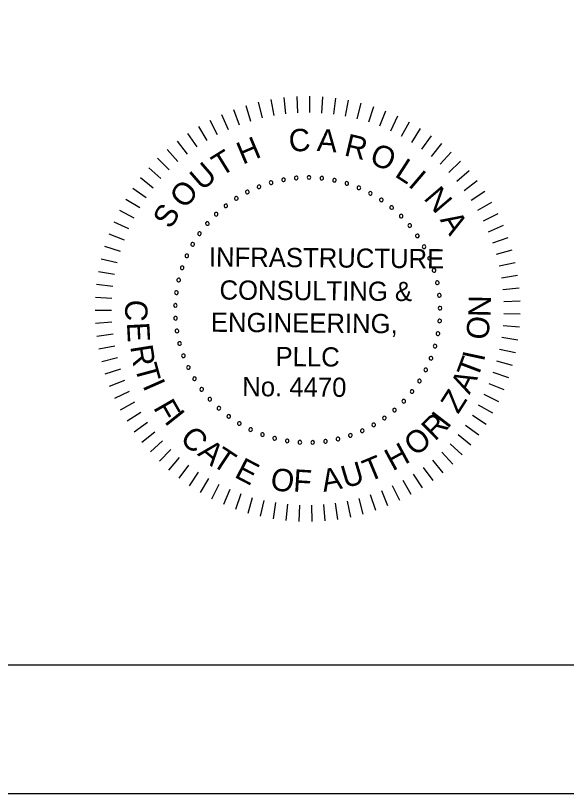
# Model space of a CAD drawing. Extents: x -125.5 to -89.4, y -5.1 to 16.9.
# Drawn here: x -100.338 to -98.192, y -5.066 to -2.039 of the extents above; entities that cross this region are included whole.
import ezdxf

# ---------------------------------------------------------------- set-up
doc = ezdxf.new("R2010")
doc.units = 0
for name, color, linetype in [('BR_BORDER LINES', 7, 'Continuous'), ('BR_TEXT', 7, 'Continuous'), ('Level 31', 7, 'Continuous')]:
    doc.layers.add(name, color=color, linetype=linetype)

msp = doc.modelspace()

# ---------------------------------------------------------------- linework, layer by layer
at = {"layer": 'BR_BORDER LINES'}
msp.add_line((-123.6994, -4.5662), (-90.0334, -4.5662), dxfattribs=at)
at = {"layer": 'BR_TEXT'}
for p, q in [((-99.2931, -2.3579), (-99.2858, -2.4212)), ((-99.2427, -2.3538), (-99.2394, -2.4174)), ((-99.1923, -2.3527), (-99.1928, -2.4164)), ((-99.1418, -2.3548), (-99.1462, -2.4183)), ((-99.0916, -2.3599), (-99.0999, -2.423)), ((-99.4412, -2.3886), (-99.4226, -2.4495)), ((-99.3925, -2.3754), (-99.3776, -2.4373)), ((-99.343, -2.3651), (-99.332, -2.4278)), ((-99.0418, -2.368), (-99.0539, -2.4305)), ((-98.9925, -2.3792), (-99.0084, -2.4408)), ((-99.489, -2.4048), (-99.4667, -2.4644)), ((-98.9441, -2.3933), (-98.9637, -2.4539)), ((-98.8966, -2.4104), (-98.9199, -2.4696)), ((-99.5813, -2.4457), (-99.5519, -2.5022)), ((-99.5358, -2.4238), (-99.5099, -2.482)), ((-98.8502, -2.4303), (-98.877, -2.488)), ((-99.6253, -2.4703), (-99.5926, -2.5249)), ((-98.8051, -2.453), (-98.8354, -2.509)), ((-98.7615, -2.4785), (-98.7952, -2.5325)), ((-99.6678, -2.4975), (-99.6318, -2.55)), ((-98.7195, -2.5065), (-98.7564, -2.5584)), ((-99.7086, -2.5273), (-99.6694, -2.5775)), ((-98.6793, -2.5371), (-98.7193, -2.5866)), ((-99.7475, -2.5595), (-99.7053, -2.6072)), ((-98.6411, -2.57), (-98.684, -2.617)), ((-99.7843, -2.5941), (-99.7393, -2.6391)), ((-99.819, -2.6308), (-99.7713, -2.673)), ((-98.6049, -2.6052), (-98.6506, -2.6495)), ((-98.571, -2.6426), (-98.6193, -2.684)), ((-99.8513, -2.6695), (-99.8012, -2.7087)), ((-98.5393, -2.6819), (-98.5901, -2.7204)), ((-99.8813, -2.7102), (-99.8288, -2.7463)), ((-98.5102, -2.7232), (-98.5632, -2.7584)), ((-99.9087, -2.7526), (-99.8541, -2.7854)), ((-98.4836, -2.7661), (-98.5387, -2.798)), ((-99.9334, -2.7965), (-99.877, -2.826)), ((-98.4597, -2.8105), (-98.5166, -2.839)), ((-99.9555, -2.842), (-99.8973, -2.8679)), ((-98.4385, -2.8563), (-98.497, -2.8813)), ((-99.9747, -2.8886), (-99.9151, -2.911)), ((-98.4202, -2.9034), (-98.4801, -2.9248)), ((-99.991, -2.9364), (-99.9302, -2.9551)), ((-98.4047, -2.9514), (-98.4659, -2.9691)), ((-100.0044, -2.9851), (-99.9426, -3)), ((-98.3922, -3.0004), (-98.4544, -3.0143)), ((-100.0149, -3.0345), (-99.9522, -3.0456)), ((-98.3828, -3.05), (-98.4456, -3.0601)), ((-100.0222, -3.0844), (-99.959, -3.0917)), ((-98.3763, -3.1), (-98.4397, -3.1063)), ((-100.0266, -3.1347), (-99.963, -3.1382)), ((-98.373, -3.1504), (-98.4366, -3.1528)), ((-100.0278, -3.1852), (-99.9641, -3.1847)), ((-98.3727, -3.2009), (-98.4363, -3.1994)), ((-100.026, -3.2356), (-99.9625, -3.2313)), ((-98.3755, -3.2513), (-98.4389, -3.2459)), ((-100.0211, -3.2859), (-99.9579, -3.2777)), ((-98.3813, -3.3014), (-98.4443, -3.2922)), ((-100.0131, -3.3357), (-99.9506, -3.3237)), ((-98.3902, -3.3511), (-98.4525, -3.3381)), ((-100.0021, -3.385), (-99.9405, -3.3692)), ((-98.4021, -3.4002), (-98.4635, -3.3834)), ((-99.9882, -3.4335), (-99.9276, -3.414)), ((-98.417, -3.4484), (-98.4773, -3.4279)), ((-99.9713, -3.4811), (-99.912, -3.4579)), ((-98.4348, -3.4957), (-98.4937, -3.4715)), ((-99.9515, -3.5276), (-99.8937, -3.5008)), ((-98.4554, -3.5417), (-98.5128, -3.514)), ((-99.929, -3.5727), (-99.8729, -3.5425)), ((-98.4789, -3.5865), (-98.5344, -3.5553)), ((-99.9037, -3.6164), (-99.8496, -3.5828)), ((-98.505, -3.6297), (-98.5585, -3.5952)), ((-99.8758, -3.6585), (-99.8239, -3.6217)), ((-99.8454, -3.6988), (-99.7958, -3.6589)), ((-98.5336, -3.6712), (-98.5849, -3.6335)), ((-98.5648, -3.7109), (-98.6137, -3.6702)), ((-99.8126, -3.7372), (-99.7655, -3.6943)), ((-98.5983, -3.7487), (-98.6447, -3.705)), ((-99.7775, -3.7735), (-99.7331, -3.7278)), ((-98.6341, -3.7843), (-98.6777, -3.7379)), ((-99.7403, -3.8076), (-99.6988, -3.7593)), ((-98.672, -3.8177), (-98.7126, -3.7687)), ((-99.701, -3.8393), (-99.6626, -3.7886)), ((-98.7118, -3.8487), (-98.7494, -3.7974)), ((-99.6599, -3.8687), (-99.6246, -3.8157)), ((-99.6171, -3.8954), (-99.5851, -3.8404)), ((-98.7534, -3.8772), (-98.7879, -3.8237)), ((-99.5728, -3.9195), (-99.5442, -3.8626)), ((-98.8416, -3.9264), (-98.8692, -3.8691)), ((-98.7967, -3.9032), (-98.8278, -3.8476)), ((-99.527, -3.9408), (-99.5019, -3.8823)), ((-99.48, -3.9594), (-99.4586, -3.8994)), ((-98.935, -3.9645), (-98.9555, -3.9042)), ((-98.8877, -3.9469), (-98.9118, -3.888)), ((-99.432, -3.975), (-99.4143, -3.9138)), ((-99.3832, -3.9876), (-99.3692, -3.9255)), ((-99.3336, -3.9973), (-99.3234, -3.9344)), ((-99.0324, -3.991), (-99.0454, -3.9286)), ((-98.9833, -3.9792), (-99.0001, -3.9178)), ((-99.2836, -4.0039), (-99.2772, -3.9406)), ((-99.2332, -4.0075), (-99.2307, -3.9438)), ((-99.1827, -4.0079), (-99.1841, -3.9443)), ((-99.1323, -4.0053), (-99.1376, -3.9419)), ((-99.0821, -3.9997), (-99.0913, -3.9367))]:
    msp.add_line(p, q, dxfattribs=at)
for centre, start, end in [((-99.2445, -2.6708), 5.0653, 185.0653), ((-99.1947, -2.6689), 359.5268, 179.5268), ((-99.3424, -2.6889), 16.1422, 196.1422), ((-99.3424, -2.6889), 196.1422, 16.1422), ((-99.2939, -2.6775), 10.6038, 190.6038), ((-99.2939, -2.6775), 190.6038, 10.6038), ((-99.2445, -2.6708), 185.0653, 5.0653), ((-99.1947, -2.6689), 179.5268, 359.5268), ((-99.145, -2.6718), 173.9884, 353.9884), ((-99.145, -2.6718), 353.9884, 173.9884), ((-99.0957, -2.6795), 168.4499, 348.4499), ((-99.0957, -2.6795), 348.4499, 168.4499), ((-99.0475, -2.6919), 162.9114, 342.9114), ((-99.0475, -2.6919), 342.9114, 162.9114), ((-99.435, -2.7255), 27.2191, 207.2191), ((-99.435, -2.7255), 207.2191, 27.2191), ((-99.3896, -2.705), 21.6807, 201.6807), ((-99.3896, -2.705), 201.6807, 21.6807), ((-99.0006, -2.709), 157.373, 337.373), ((-99.0006, -2.709), 337.373, 157.373), ((-98.9557, -2.7304), 331.8345, 151.8345), ((-99.4782, -2.7503), 32.7576, 212.7576), ((-99.4782, -2.7503), 212.7576, 32.7576), ((-98.9557, -2.7304), 151.8345, 331.8345), ((-98.913, -2.7561), 146.2961, 326.2961), ((-98.913, -2.7561), 326.2961, 146.2961), ((-99.5188, -2.7792), 38.2961, 218.2961), ((-99.5188, -2.7792), 218.2961, 38.2961), ((-98.873, -2.7858), 140.7576, 320.7576), ((-98.873, -2.7858), 320.7576, 140.7576), ((-99.5564, -2.8119), 43.8345, 223.8345), ((-99.5564, -2.8119), 223.8345, 43.8345), ((-98.836, -2.8192), 135.2191, 315.2191), ((-98.836, -2.8192), 315.2191, 135.2191), ((-99.5907, -2.848), 49.373, 229.373), ((-99.5907, -2.848), 229.373, 49.373), ((-98.8024, -2.8561), 129.6807, 309.6807), ((-98.8024, -2.8561), 309.6807, 129.6807), ((-99.6214, -2.8873), 54.9114, 234.9114), ((-99.6214, -2.8873), 234.9114, 54.9114), ((-98.7726, -2.896), 124.1422, 304.1422), ((-98.7726, -2.896), 304.1422, 124.1422), ((-99.6481, -2.9293), 60.4499, 240.4499), ((-99.6481, -2.9293), 240.4499, 60.4499), ((-98.7467, -2.9386), 118.6038, 298.6038), ((-98.7467, -2.9386), 298.6038, 118.6038), ((-99.6706, -2.9738), 65.9884, 245.9884), ((-99.6706, -2.9738), 245.9884, 65.9884), ((-98.7251, -2.9835), 113.0653, 293.0653), ((-98.7251, -2.9835), 293.0653, 113.0653), ((-99.6888, -3.0202), 71.5268, 251.5268), ((-99.6888, -3.0202), 251.5268, 71.5268), ((-98.7079, -3.0302), 107.5268, 287.5268), ((-98.7079, -3.0302), 287.5268, 107.5268), ((-99.7024, -3.0681), 77.0653, 257.0653), ((-99.7024, -3.0681), 257.0653, 77.0653), ((-98.6953, -3.0785), 101.9884, 281.9884), ((-98.6953, -3.0785), 281.9884, 101.9884), ((-99.7113, -3.1172), 82.6038, 262.6038), ((-99.7113, -3.1172), 262.6038, 82.6038), ((-98.6874, -3.1277), 96.4499, 276.4499), ((-98.6874, -3.1277), 276.4499, 96.4499), ((-99.7154, -3.1668), 88.1422, 268.1422), ((-99.7154, -3.1668), 268.1422, 88.1422), ((-98.6843, -3.1774), 90.9114, 270.9114), ((-98.6843, -3.1774), 270.9114, 90.9114), ((-99.7147, -3.2167), 93.6807, 273.6807), ((-99.7147, -3.2167), 273.6807, 93.6807), ((-98.686, -3.2272), 85.373, 265.373), ((-98.686, -3.2272), 265.373, 85.373), ((-99.7092, -3.2662), 99.2191, 279.2191), ((-99.7092, -3.2662), 279.2191, 99.2191), ((-98.6926, -3.2766), 79.8345, 259.8345), ((-98.6926, -3.2766), 259.8345, 79.8345), ((-99.6989, -3.3149), 104.7576, 284.7576), ((-99.6989, -3.3149), 284.7576, 104.7576), ((-98.7038, -3.3251), 74.2961, 254.2961), ((-98.7038, -3.3251), 254.2961, 74.2961), ((-99.684, -3.3625), 110.2961, 290.2961), ((-99.684, -3.3625), 290.2961, 110.2961), ((-98.7197, -3.3724), 68.7576, 248.7576), ((-98.7197, -3.3724), 248.7576, 68.7576), ((-99.6646, -3.4084), 115.8345, 295.8345), ((-99.6646, -3.4084), 295.8345, 115.8345), ((-98.7401, -3.4178), 63.2191, 243.2191), ((-98.7401, -3.4178), 243.2191, 63.2191), ((-99.6408, -3.4522), 121.373, 301.373), ((-99.6408, -3.4522), 301.373, 121.373), ((-98.7647, -3.4611), 57.6807, 237.6807), ((-98.7647, -3.4611), 237.6807, 57.6807), ((-99.6129, -3.4935), 126.9114, 306.9114), ((-99.6129, -3.4935), 306.9114, 126.9114), ((-98.7934, -3.5019), 52.1422, 232.1422), ((-98.7934, -3.5019), 232.1422, 52.1422), ((-99.5812, -3.5319), 132.4499, 312.4499), ((-99.5812, -3.5319), 312.4499, 132.4499), ((-98.826, -3.5396), 46.6038, 226.6038), ((-98.826, -3.5396), 226.6038, 46.6038), ((-99.5459, -3.5671), 137.9884, 317.9884), ((-99.5459, -3.5671), 317.9884, 137.9884), ((-98.862, -3.5741), 41.0653, 221.0653), ((-98.862, -3.5741), 221.0653, 41.0653), ((-99.5074, -3.5987), 143.5268, 323.5268), ((-99.5074, -3.5987), 323.5268, 143.5268), ((-98.9012, -3.6049), 35.5268, 215.5268), ((-98.9012, -3.6049), 215.5268, 35.5268), ((-99.466, -3.6264), 149.0653, 329.0653), ((-99.466, -3.6264), 329.0653, 149.0653), ((-98.9431, -3.6317), 29.9884, 209.9884), ((-98.9431, -3.6317), 209.9884, 29.9884), ((-99.4221, -3.65), 154.6038, 334.6038), ((-99.4221, -3.65), 334.6038, 154.6038), ((-99.3761, -3.6693), 340.1422, 160.1422), ((-98.9875, -3.6545), 24.4499, 204.4499), ((-98.9875, -3.6545), 204.4499, 24.4499), ((-99.3761, -3.6693), 160.1422, 340.1422), ((-99.3285, -3.684), 165.6807, 345.6807), ((-99.3285, -3.684), 345.6807, 165.6807), ((-99.2797, -3.6941), 351.2191, 171.2191), ((-99.2797, -3.6941), 171.2191, 351.2191), ((-99.2302, -3.6994), 356.7576, 176.7576), ((-99.1803, -3.6999), 2.2961, 182.2961), ((-99.1307, -3.6956), 7.8345, 187.8345), ((-99.0817, -3.6865), 13.373, 193.373), ((-99.0817, -3.6865), 193.373, 13.373), ((-99.0338, -3.6728), 18.9114, 198.9114), ((-99.0338, -3.6728), 198.9114, 18.9114), ((-99.2302, -3.6994), 176.7576, 356.7576), ((-99.1803, -3.6999), 182.2961, 2.2961), ((-99.1307, -3.6956), 187.8345, 7.8345)]:
    msp.add_arc(centre, 0.00701, start, end, dxfattribs=at)
at = {"layer": 'Level 31'}
msp.add_lwpolyline([(-125.5328, 16.9339), (-125.5328, -5.0661), (-89.5328, -5.0661), (-89.5328, 16.9339)], dxfattribs=at)

# ---------------------------------------------------------------- texts
at = {"layer": 'BR_TEXT'}
for s, height, rotation, p in [('C', 0.0872, 4.7281, (-99.2702, -2.5703)), ('A', 0.0872, 355.6981, (-99.1657, -2.5654)), ('H', 0.0872, 22.7882, (-99.453, -2.6197)), ('R', 0.0872, 346.6681, (-99.0615, -2.5824)), ('O', 0.0872, 337.638, (-98.9637, -2.6122)), ('T', 0.0872, 31.8182, (-99.5379, -2.6674)), ('L', 0.0872, 327.108, (-98.8649, -2.6626)), ('U', 0.0872, 40.8482, (-99.6112, -2.7235)), ('I', 0.0872, 319.578, (-98.8123, -2.7005)), ('O', 0.0872, 49.8782, (-99.6782, -2.7945)), ('N', 0.0872, 310.548, (-98.7515, -2.7512)), ('S', 0.0872, 58.9083, (-99.7336, -2.8727)), ('A', 0.0872, 301.5179, (-98.6864, -2.8336)), ('INFRASTRUCTURE', 0.074771, 359.5268, (-99.585, -3.0152)), ('CONSULTING &', 0.074771, 359.5268, (-99.5437, -3.1438)), ('N', 0.0872, 89.2085, (-98.4872, -3.2124)), ('C', 0.0872, 267.025, (-99.9086, -3.1426)), ('ENGINEERING,', 0.074771, 359.5268, (-99.5773, -3.2693)), ('E', 0.0872, 273.025, (-99.9042, -3.2342)), ('O', 0.0872, 83.2085, (-98.4982, -3.3038)), ('R', 0.0872, 279.025, (-99.8914, -3.3265)), ('PLLC', 0.07477, 359.5268, (-99.3256, -3.4028)), ('I', 0.0872, 77.9093, (-98.5137, -3.3881)), ('T', 0.0872, 285.025, (-99.874, -3.4053)), ('T', 0.0872, 69.3954, (-98.5394, -3.4556)), ('No. 4470', 0.07477, 359.5268, (-99.4551, -3.5197)), ('A', 0.0872, 63.3954, (-98.5702, -3.516)), ('I', 0.0872, 293.7713, (-99.8443, -3.4784)), ('Z', 0.0872, 57.3954, (-98.6141, -3.5923)), ('F', 0.0872, 299.7713, (-99.8031, -3.5644)), ('I', 0.0872, 308.5268, (-99.761, -3.6183)), ('R', 0.0872, 44.5268, (-98.7045, -3.6973)), ('I', 0.0872, 52.3339, (-98.6551, -3.65)), ('C', 0.0872, 314.5268, (-99.7017, -3.6884)), ('O', 0.0872, 38.5268, (-98.7811, -3.7572)), ('A', 0.0872, 320.5268, (-99.6325, -3.747)), ('T', 0.0872, 326.5268, (-99.5781, -3.7855)), ('H', 0.0872, 28.5268, (-98.8692, -3.8132)), ('T', 0.0872, 22.5268, (-98.9624, -3.855)), ('E', 0.0872, 332.5268, (-99.4895, -3.8332)), ('U', 0.0872, 16.5268, (-99.0541, -3.8794)), ('O', 0.0872, 350.5268, (-99.3494, -3.8821)), ('F', 0.0872, 356.5268, (-99.2579, -3.8912)), ('A', 0.0872, 10.5268, (-99.138, -3.8929))]:
    msp.add_text(s, height=height, rotation=rotation, dxfattribs=at).set_placement(p)

doc.saveas('drawing.dxf')
